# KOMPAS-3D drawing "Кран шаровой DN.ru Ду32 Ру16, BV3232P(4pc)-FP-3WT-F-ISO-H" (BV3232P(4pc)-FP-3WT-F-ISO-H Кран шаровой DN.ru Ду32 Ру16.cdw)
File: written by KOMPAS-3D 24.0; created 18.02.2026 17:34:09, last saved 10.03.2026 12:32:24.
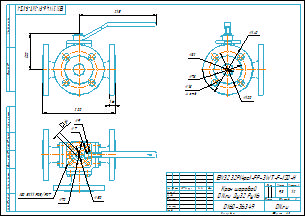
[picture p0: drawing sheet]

Document properties: Автор: R2D2; Форматы листов документа: A3; Полное имя файла: BV3232P(4pc)-FP-3WT-F-ISO-H Кран шаровой DN.ru Ду32 Ру16.m3d; Масса: 9.3; Наименование: Кран шаровой DN.ru Ду32 Ру16; Количество листов документа: 1; Примечание: D160-36349

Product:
- Part/product: Кран шаровой DN.ru Ду32 Ру16  | designation BV3232P(4pc)-FP-3WT-F-ISO-H
    Масса: 9.3
    Раздел спецификации: Прочие изделия
    Примечание: D160-36349

Views: Вид 1, Спереди, Проекционный вид 2
Referenced files in E:\Работа\Зайцев\BV3232P(4pc)-FP-3WL-F-ISO-H Кран шаровой DN.ru Ду15-100 Ру16\DN32\: BV3232P(4pc)-FP-3WL-F-ISO-H Кран шаровой DN.ru Ду32 Ру16.m3d
Referenced files in E:\Работа\Зайцев\BV3232P(4pc)-FP-3WT-F-ISO-H Кран шаровой DN.ru Ду15-100 Ру16\DN32\: BV3232P(4pc)-FP-3WT-F-ISO-H Кран шаровой DN.ru Ду32 Ру16.m3d
Referenced files in E:\Работа\Зайцев\Для компаса\: чертеж DN.ru А3.cdt
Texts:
  BV3232P(4pc)-FP-3WT-F-ISO-H
  чертеж DN.ru А3.cdt
  Кран шаровой
  DN.ru Ду32 Ру16
  Кран шаровой DN.ru Ду32 Ру16
  BV3232P(4pc)-FP-3WT-F-ISO-H Кран шаровой DN.ru Ду32 Ру16
Dimensions and other numbers on the sheet: 0; 3; 2; 4; 215; 100; 200; 16; 140; 78; 18; 4 отв.; 32; 1:2; 1; 9,3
